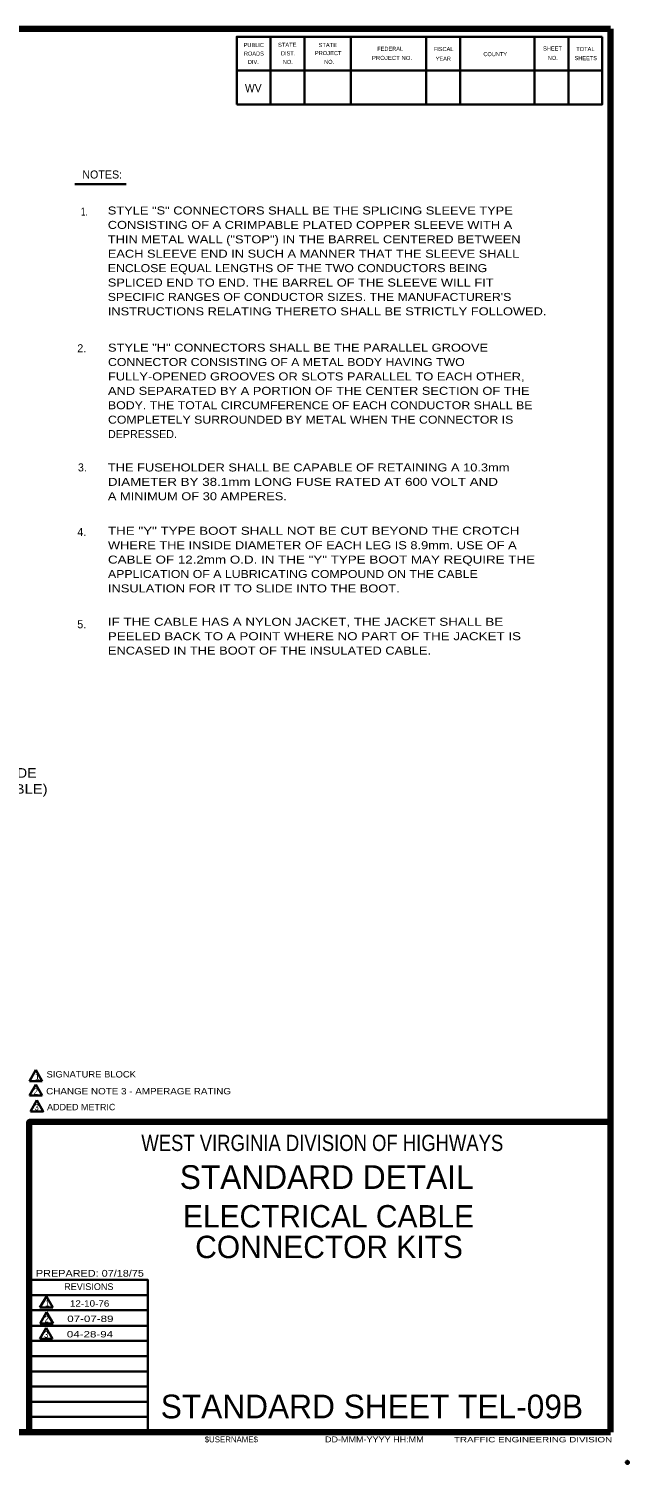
# Model space of a CAD drawing. Extents: x -8 to 705, y -12 to 442.
# Drawn here: x 517.5 to 704.9, y -11.5 to 436.6 of the extents above; entities that cross this region are included whole.
import ezdxf
from ezdxf.enums import TextEntityAlignment as Align

# ---------------------------------------------------------------- set-up
doc = ezdxf.new("R2010")
doc.units = 0
doc.header["$LTSCALE"] = 1.2
doc.header["$PDMODE"] = 32
doc.header["$PDSIZE"] = 0.6
doc.layers.add('1', color=7, linetype='Continuous', lineweight=53)
doc.layers.add('61', color=7, linetype='Continuous', lineweight=35)

msp = doc.modelspace()

# ---------------------------------------------------------------- linework, layer by layer
at = {"layer": '1', "lineweight": 158}
for q in [(699.308, 436.624), (699.308, 95.124), (39.641, -1.793)]:
    msp.add_line((699.308, -1.793), q, dxfattribs=at)
at = {"layer": '1', "lineweight": 13}
msp.add_line((699.308, -1.793), (699.308, 436.624), dxfattribs=at)
at = {"layer": '1', "lineweight": 35}
for p, q in [((531.868, 388.018), (547.973, 388.018)), ((519.721, 111.359), (517.721, 107.895)), ((521.721, 107.895), (517.721, 107.895)), ((519.721, 111.359), (521.721, 107.895)), ((519.721, 106.825), (517.721, 103.361)), ((521.721, 103.361), (517.721, 103.361)), ((519.721, 106.825), (521.721, 103.361)), ((520.003, 101.881), (518.003, 98.417)), ((554.724, 41.041), (517.641, 41.041)), ((522.987, 40.582), (520.987, 37.118)), ((522.987, 40.582), (524.987, 37.118)), ((554.724, 36.291), (517.641, 36.291)), ((524.987, 37.118), (520.987, 37.118)), ((554.724, 31.457), (517.641, 31.457)), ((523.077, 35.661), (521.077, 32.197)), ((525.077, 32.197), (521.077, 32.197)), ((523.077, 35.661), (525.077, 32.197)), ((522.948, 30.836), (520.948, 27.372)), ((524.948, 27.372), (520.948, 27.372)), ((522.948, 30.836), (524.948, 27.372)), ((554.724, 26.707), (517.641, 26.707)), ((554.724, 21.957), (517.641, 21.957)), ((554.724, 17.207), (517.641, 17.207)), ((554.724, 12.457), (517.641, 12.457)), ((554.724, 7.707), (517.641, 7.707)), ((554.724, 2.957), (517.641, 2.957))]:
    msp.add_line(p, q, dxfattribs=at)
at = {"layer": '1', "lineweight": 158}
for points in [[(699.308, 436.624), (39.557, 436.541), (39.641, -1.793)], [(517.641, -1.793), (517.641, 95.124), (699.308, 95.124)]]:
    msp.add_lwpolyline(points, dxfattribs=at)
at = {"layer": '1', "lineweight": 35}
for points in [[(520.003, 101.881), (522.003, 98.417), (518.003, 98.417)], [(554.724, -1.793), (554.724, 45.791), (517.641, 45.791)]]:
    msp.add_lwpolyline(points, dxfattribs=at)
at = {"layer": '1'}
msp.add_point((704.558, -11.209), dxfattribs=at)
at = {"layer": '61'}
for p, q in [((593.058, 434.124), (593.058, 412.957)), ((603.641, 434.124), (603.641, 412.957)), ((618.141, 434.124), (618.141, 412.957)), ((641.724, 434.124), (641.724, 412.957)), ((652.308, 434.124), (652.308, 412.957)), ((675.558, 434.124), (675.558, 412.957)), ((686.141, 434.124), (686.141, 412.957)), ((696.724, 423.541), (582.474, 423.541))]:
    msp.add_line(p, q, dxfattribs=at)
at = {"layer": '61', "lineweight": 53}
for q in [(572.058, -1.793), (572.058, -1.793), (572.058, -1.793), (572.308, -1.793), (572.308, -1.793)]:
    msp.add_line((699.308, -1.793), q, dxfattribs=at)
at = {"layer": '61'}
for points in [[(696.724, 434.124), (582.474, 434.124), (582.474, 412.957)], [(696.724, 434.124), (696.724, 412.957), (582.474, 412.957)]]:
    msp.add_lwpolyline(points, dxfattribs=at)

# ---------------------------------------------------------------- texts
at = {"layer": '1'}
for s, height, width, p in [('WV', 2.54, 0.95, (585.058, 416.791)), ('STYLE "S" CONNECTORS SHALL BE THE SPLICING SLEEVE TYPE', 2.5, 1.2, (542.183, 378.581)), ('1.', 2.5, 0.65, (533.827, 378.268)), ('CONSISTING OF A CRIMPABLE PLATED COPPER SLEEVE WITH A', 2.5, 1.2, (542.183, 374.081)), ('THIN METAL WALL ("STOP") IN THE BARREL CENTERED BETWEEN', 2.5, 1.2, (542.183, 369.581)), ('EACH SLEEVE END IN SUCH A MANNER THAT THE SLEEVE SHALL', 2.5, 1.2, (542.183, 365.081)), ('ENCLOSE EQUAL LENGTHS OF THE TWO CONDUCTORS BEING', 2.5, 1.15, (542.183, 360.581)), ('SPLICED END TO END. THE BARREL OF THE SLEEVE WILL FIT', 2.5, 1.2, (542.183, 356.081)), ("SPECIFIC RANGES OF CONDUCTOR SIZES. THE MANUFACTURER'S", 2.5, 1.15, (542.183, 351.581)), ('INSTRUCTIONS RELATING THERETO SHALL BE STRICTLY FOLLOWED. ', 2.5, 1.2, (542.183, 347.081)), ('STYLE "H" CONNECTORS SHALL BE THE PARALLEL GROOVE', 2.5, 1.2, (542.247, 335.746)), ('CONNECTOR CONSISTING OF A METAL BODY HAVING TWO', 2.5, 1.15, (542.247, 331.246)), ('FULLY-OPENED GROOVES OR SLOTS PARALLEL TO EACH OTHER,', 2.5, 1.2, (542.247, 326.746)), ('AND SEPARATED BY A PORTION OF THE CENTER SECTION OF THE', 2.5, 1.2, (542.247, 322.246)), ('BODY. THE TOTAL CIRCUMFERENCE OF EACH CONDUCTOR SHALL BE', 2.5, 1.15, (542.247, 317.746)), ('COMPLETELY SURROUNDED BY METAL WHEN THE CONNECTOR IS', 2.5, 1.15, (542.247, 313.246)), ('THE FUSEHOLDER SHALL BE CAPABLE OF RETAINING A 10.3mm', 2.5, 1.2, (542.208, 298.316)), ('DIAMETER BY 38.1mm LONG FUSE RATED AT 600 VOLT AND', 2.5, 1.25, (542.208, 293.816)), ('A MINIMUM OF 30 AMPERES. ', 2.5, 1.2, (542.208, 289.316)), ('THE "Y" TYPE BOOT SHALL NOT BE CUT BEYOND THE CROTCH', 2.5, 1.25, (542.242, 278.534)), ('WHERE THE INSIDE DIAMETER OF EACH LEG IS 8.9mm. USE OF A', 2.5, 1.2, (542.242, 274.034)), ('CABLE OF 12.2mm O.D. IN THE "Y" TYPE BOOT MAY REQUIRE THE', 2.5, 1.25, (542.242, 269.534)), ('APPLICATION OF A LUBRICATING COMPOUND ON THE CABLE', 2.5, 1.15, (542.242, 265.034)), ('INSULATION FOR IT TO SLIDE INTO THE BOOT.', 2.5, 1.2, (542.242, 260.534)), ('IF THE CABLE HAS A NYLON JACKET, THE JACKET SHALL BE', 2.5, 1.25, (542.219, 250.105)), ('PEELED BACK TO A POINT WHERE NO PART OF THE JACKET IS', 2.5, 1.25, (542.219, 245.605)), ('ENCASED IN THE BOOT OF THE INSULATED CABLE.', 2.5, 1.2, (542.219, 241.105)), ('SIGNATURE BLOCK', 2, 1.1, (523.039, 109.008)), ('2', 2, 0.9, (519.002, 103.664)), ('CHANGE NOTE 3 - AMPERAGE RATING', 2, 1.15, (522.92, 103.724)), ('3', 2, 0.9, (519.284, 98.72)), ('ADDED METRIC', 2, 1.05, (523.202, 98.779)), ('PREPARED: 07/18/75', 2.114, 1.2, (519.724, 46.791)), ('2', 2, 0.9, (522.397, 32.543)), ('3', 2, 0.9, (522.268, 27.718)), ('DD-MMM-YYYY HH:MM', 1.833, 1.15, (610.058, -4.959)), ('TRAFFIC ENGINEERING DIVISION', 1.693, 1.35, (650.391, -4.959))]:
    msp.add_text(s, height=height, dxfattribs=dict(at, width=width)).set_placement(p)
for s, height, p in [('NOTES:', 2.5, (534.219, 389.828)), ('2.', 2.5, (532.652, 335.555)), ('DEPRESSED.', 2.5, (542.247, 308.746)), ('3.', 2.5, (532.848, 298.327)), ('4.', 2.5, (532.652, 278.146)), ('5.', 2.5, (532.652, 249.344)), ('1', 2, (519.418, 108.296)), ('REVISIONS', 2.114, (528.558, 42.624)), ('1', 2, (522.586, 37.492)), ('STANDARD SHEET TEL-09B', 7.401, (558.724, 2.541)), ('$USERNAME$', 1.833, (572.474, -4.959))]:
    msp.add_text(s, height=height, dxfattribs=at).set_placement(p)
for s, height, width, p in [('LINE SIDE', 3, 1.1, (509.263, 202.645)), ('(SEE TABLE)', 3, 1.15, (509.263, 197.645)), ('WEST VIRGINIA DIVISION OF HIGHWAYS', 5.074, 0.85, (609.224, 86.041)), ('12-10-76', 2, 1.15, (536.501, 37.42)), ('07-07-89', 2, 1.35, (536.739, 32.632)), ('04-28-94', 2, 1.35, (536.618, 27.807))]:
    msp.add_text(s, height=height, dxfattribs=dict(at, width=width)).set_placement(p, align=Align.CENTER)
for s, height, p in [('STANDARD DETAIL', 7.401, (610.599, 74.207)), ('ELECTRICAL CABLE', 6.993, (611.163, 62.163)), ('CONNECTOR KITS', 6.993, (611.331, 52.592))]:
    msp.add_text(s, height=height, dxfattribs=at).set_placement(p, align=Align.CENTER)
at = {"layer": '61'}
for s, height, rotation, p in [('PUBLIC', 1.271, 0.033, (584.641, 430.874)), ('FEDERAL', 1.27, 0.007, (626.391, 429.707)), ('FISCAL', 1.271, 359.942, (644.058, 429.624)), ('SHEET', 1.271, 0.059, (678.224, 429.791)), ('ROADS', 1.27, 0.124, (584.724, 428.207)), ('DIV.', 1.27, 359.932, (585.974, 425.624)), ('DIST.', 1.27, 0.056, (596.308, 428.291)), ('YEAR', 1.27, 0.105, (644.641, 426.624)), ('COUNTY', 1.269, 0.069, (659.558, 428.041)), ('SHEETS', 1.269, 359.959, (688.058, 426.791))]:
    msp.add_text(s, height=height, rotation=rotation, dxfattribs=at).set_placement(p)
for s, height, rotation, width, p in [('STATE', 1.271, 0.059, 1.05, (595.391, 430.957)), ('STATE', 1.271, 0.059, 1.05, (608.058, 430.874)), ('TOTAL', 1.27, 359.926, 1.05, (688.558, 429.624)), ('NO.', 1.27, 359.852, 0.9, (596.891, 425.624)), ('PROJECT', 1.27, 359.908, 1.05, (606.891, 428.374)), ('NO.', 1.271, 0.225, 0.9, (609.808, 425.624)), ('PROJECT NO.', 1.27, 359.922, 1.1, (624.724, 426.874)), ('NO.', 1.27, 359.852, 0.9, (679.724, 426.874))]:
    msp.add_text(s, height=height, rotation=rotation, dxfattribs=dict(at, width=width)).set_placement(p)

doc.saveas('drawing.dxf')
